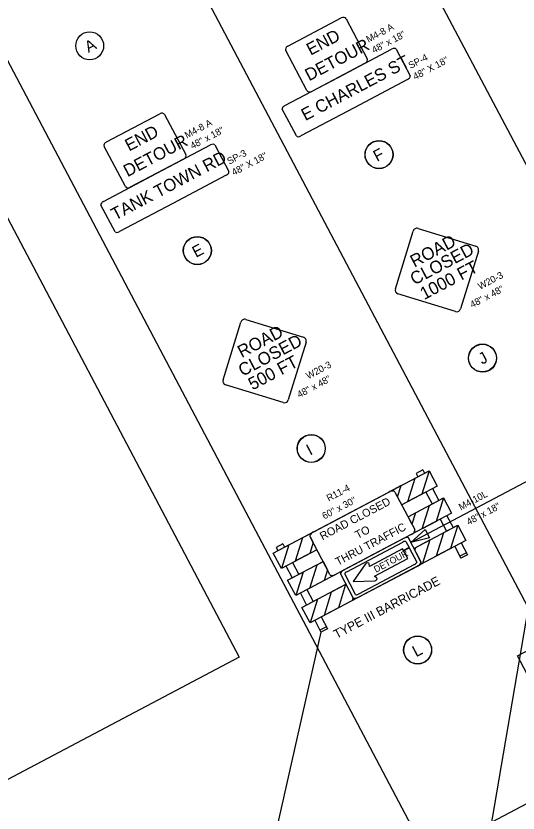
# Model space of a CAD drawing. Extents: x 1487176 to 2935813, y 497724 to 1002340.
# Drawn here: x 1488583 to 1489024, y 498480 to 499179 of the extents above; entities that cross this region are included whole.
import ezdxf

# ---------------------------------------------------------------- set-up
doc = ezdxf.new("R2010")
doc.units = 0
for name, color, linetype in [('DEV TYPE 3 BARRICADE WITH R11-4 M4-10L CELL', 7, 'Continuous'), ('Gray Area Fill Shapes', 7, 'Continuous'), ('GS M4-8 CELL', 7, 'Continuous'), ('Scratch_Level_0', 7, 'Continuous'), ('Scratch_Level_1', 7, 'Continuous'), ('Sheet Block Title CELL', 7, 'Continuous'), ('Sheet Breakdown Map CELL', 7, 'Continuous'), ('WZ OSDHWYEND CELL', 7, 'Continuous'), ('WZ OSDHWYR CELL', 7, 'Continuous'), ('WZ OSDHWYS CELL', 7, 'Continuous'), ('WZ OSDR CELL', 7, 'Continuous'), ('WZ RC1000 CELL', 7, 'Continuous'), ('WZ RC500 CELL', 7, 'Continuous')]:
    doc.layers.add(name, color=color, linetype=linetype)

msp = doc.modelspace()

# ---------------------------------------------------------------- linework, layer by layer
at = {"layer": 'DEV TYPE 3 BARRICADE WITH R11-4 M4-10L CELL'}
for p, q in [((1488809.03, 498707.77), (1488945.87, 498780.03)), ((1488933.56, 498773.53), (1488945.87, 498780.03)), ((1488940.27, 498780.78), (1488934.46, 498777.72)), ((1488934.46, 498777.72), (1488936, 498774.81)), ((1488945.87, 498780.03), (1488939.54, 498759.53)), ((1488940.27, 498780.78), (1488941.8, 498777.88)), ((1488945.87, 498780.03), (1488952.95, 498766.61)), ((1488921.24, 498767.02), (1488910.42, 498761.31)), ((1488918.17, 498757.08), (1488921.24, 498767.02)), ((1488927.22, 498753.02), (1488933.56, 498773.53)), ((1488929.73, 498717.15), (1489035.09, 498772.78)), ((1488915.89, 498761.41), (1488918.17, 498757.08)), ((1488915.89, 498761.41), (1488915.89, 498761.41)), ((1488952.95, 498766.61), (1488921.82, 498750.17)), ((1488943.08, 498761.4), (1488948.6, 498750.94)), ((1488948.89, 498764.46), (1488954.41, 498754.01)), ((1488939.54, 498759.53), (1488927.22, 498753.02)), ((1488927.34, 498739.72), (1488958.47, 498756.16)), ((1488946.16, 498749.65), (1488958.47, 498756.16)), ((1488958.47, 498756.16), (1488952.14, 498735.65)), ((1488958.47, 498756.16), (1488965.56, 498742.74)), ((1488939.83, 498729.15), (1488946.16, 498749.65)), ((1488965.56, 498742.74), (1488828.72, 498670.49)), ((1488927.34, 498739.72), (1488933.85, 498743.15)), ((1488930.78, 498733.21), (1488927.34, 498739.72)), ((1488933.85, 498743.15), (1488930.78, 498733.21)), ((1488961.49, 498740.59), (1488967.01, 498730.14)), ((1488932.49, 498711.91), (1488971.08, 498732.28)), ((1488952.14, 498735.65), (1488939.83, 498729.15)), ((1488955.69, 498737.53), (1488961.21, 498727.07)), ((1488958.77, 498725.78), (1488971.08, 498732.28)), ((1488971.08, 498732.28), (1488964.75, 498711.78)), ((1488971.08, 498732.28), (1488978.16, 498718.87)), ((1488834.99, 498721.48), (1488844.51, 498726.51)), ((1488952.43, 498705.28), (1488958.77, 498725.78)), ((1488828.66, 498700.98), (1488834.99, 498721.48)), ((1488841.31, 498722.04), (1488843.94, 498717.07)), ((1488978.16, 498718.87), (1488841.33, 498646.61)), ((1488934.14, 498712.78), (1488946.45, 498719.28)), ((1488946.45, 498719.28), (1488940.12, 498698.78)), ((1488809.03, 498707.77), (1488822.68, 498714.98)), ((1488817.37, 498715.89), (1488811.56, 498712.82)), ((1488811.56, 498712.82), (1488813.1, 498709.92)), ((1488822.68, 498714.98), (1488816.12, 498694.36)), ((1488817.37, 498715.89), (1488818.91, 498712.99)), ((1488843.94, 498717.07), (1488840.98, 498707.48)), ((1488873.57, 498691.42), (1488922.82, 498717.49)), ((1488922.6, 498711.42), (1488893.42, 498696.01)), ((1488923.35, 498709.99), (1488922.6, 498711.42)), ((1488928.3, 498712.61), (1488923.35, 498709.99)), ((1488923.43, 498709.84), (1488928.39, 498712.45)), ((1488925.51, 498717.9), (1488928.3, 498712.61)), ((1488928.39, 498712.45), (1488934.99, 498699.78)), ((1488933.36, 498710.26), (1488934.14, 498712.78)), ((1488964.75, 498711.78), (1488952.43, 498705.28)), ((1488968.29, 498713.65), (1488973.81, 498703.2)), ((1488974.1, 498716.72), (1488979.62, 498706.27)), ((1488816.12, 498694.36), (1488809.03, 498707.77)), ((1488816.12, 498694.36), (1488809.03, 498707.77)), ((1488847.25, 498710.79), (1488816.12, 498694.36)), ((1488840.98, 498707.48), (1488828.66, 498700.98)), ((1488927.09, 498702.91), (1488923.43, 498709.84)), ((1488938.43, 498700.67), (1488933.36, 498710.26)), ((1488978.7, 498708.01), (1488972.89, 498704.94)), ((1488979.62, 498706.27), (1488973.81, 498703.2)), ((1488821.64, 498683.9), (1488852.77, 498700.34)), ((1488825.99, 498699.57), (1488831.51, 498689.12)), ((1488841.27, 498677.11), (1488847.6, 498697.61)), ((1488847.6, 498697.61), (1488852.77, 498700.34)), ((1488890.13, 498698.42), (1488879.03, 498682.91)), ((1488933.12, 498697.83), (1488883.9, 498671.84)), ((1488893.42, 498696.01), (1488893.27, 498698.4)), ((1488897.92, 498687.51), (1488927.09, 498702.91)), ((1488940.12, 498698.78), (1488936.12, 498696.67)), ((1488820.18, 498696.5), (1488825.7, 498686.05)), ((1488821.64, 498683.9), (1488835.29, 498691.11)), ((1488835.29, 498691.11), (1488828.72, 498670.49)), ((1488883.39, 498668.83), (1488936.09, 498696.65)), ((1488828.72, 498670.49), (1488821.64, 498683.9)), ((1488828.72, 498670.49), (1488821.64, 498683.9)), ((1488853.58, 498683.61), (1488841.27, 498677.11)), ((1488881.29, 498671.43), (1488871.74, 498689.52)), ((1488879.03, 498682.91), (1488898.02, 498683.48)), ((1488899.77, 498686.08), (1488897.92, 498687.51)), ((1488834.24, 498660.03), (1488872.83, 498680.41)), ((1488860.2, 498673.74), (1488872.52, 498680.24)), ((1488872.52, 498680.24), (1488866.18, 498659.74)), ((1488832.79, 498672.63), (1488838.31, 498662.18)), ((1488838.6, 498675.7), (1488844.12, 498665.24)), ((1488853.87, 498653.24), (1488860.2, 498673.74)), ((1488834.24, 498660.03), (1488847.89, 498667.24)), ((1488847.89, 498667.24), (1488841.33, 498646.61)), ((1488883.39, 498668.83), (1488878.5, 498666.24)), ((1488878.5, 498666.24), (1488879.23, 498668.62)), ((1488841.33, 498646.61), (1488834.24, 498660.03)), ((1488841.33, 498646.61), (1488834.24, 498660.03)), ((1488866.18, 498659.74), (1488853.87, 498653.24)), ((1488845.39, 498648.76), (1488850.91, 498638.31)), ((1488851.2, 498651.83), (1488856.72, 498641.37)), ((1488855.8, 498643.12), (1488849.99, 498640.05)), ((1488856.72, 498641.37), (1488850.91, 498638.31))]:
    msp.add_line(p, q, dxfattribs=at)
for points in [[(1488844.51, 498726.51), (1488910.39, 498761.29)], [(1488915.89, 498761.41), (1488933.28, 498728.48)], [(1488858.7, 498689.1), (1488841.31, 498722.04)], [(1488930.08, 498724), (1488864.2, 498689.22)], [(1488923.49, 498720.52), (1488870.79, 498692.7)], [(1488938.89, 498699.8), (1488927.66, 498721.06)], [(1488852.77, 498700.34), (1488856.54, 498693.19), (1488853.58, 498683.61)], [(1488868, 498689.56), (1488879.23, 498668.3)]]:
    msp.add_lwpolyline(points, dxfattribs=at)
msp.add_lwpolyline([(1488946.16, 498721.18), (1488929.73, 498717.15), (1488942.33, 498728.44)], close=True, dxfattribs=at)
msp.add_lwpolyline([(1488946.16, 498721.18), (1488929.73, 498717.15), (1488942.33, 498728.44)], close=True, dxfattribs=at)
for centre, major_axis, ratio, start_param, end_param in [((1488911.54, 498759.12), (4.35, 2.3), 0.5, 0, 1.570796), ((1488911.54, 498759.12), (4.35, 2.3), 0.5, 0, 1.570881), ((1488845.66, 498724.33), (-4.35, -2.3), 0.5, 4.712162, 6.283185), ((1488845.66, 498724.33), (-4.35, -2.3), 0.5, 4.712162, 6.283185), ((1488928.93, 498726.18), (-4.35, -2.3), 0.5, 1.570796, 3.141593), ((1488923.21, 498716.69), (2.24, 1.18), 0.337508, 6.283183, 7.85379), ((1488924.18, 498719.22), (3.48, 1.84), 0.375009, 0, 1.571024), ((1488891.59, 498697.91), (-1.6, -0.84), 0.720018, 2.830616, 5.313575), ((1488932.72, 498698.59), (2.24, 1.18), 0.337508, 4.712575, 6.283183), ((1488934.95, 498698.83), (-3.48, -1.84), 0.625, 1.570796, 3.141593), ((1488935.4, 498697.96), (3.48, 1.84), 0.375009, 4.712389, 6.283185), ((1488871.48, 498691.39), (-3.48, -1.84), 0.375009, 4.712389, 6.283185), ((1488873.98, 498690.7), (-2.24, -1.18), 0.337508, 4.712198, 6.283193), ((1488863.05, 498691.4), (-4.35, -2.3), 0.5, 0, 1.570796), ((1488898.45, 498684.92), (-1.6, -0.84), 0.720018, 0.969609, 3.452568), ((1488883.5, 498672.6), (-2.24, -1.18), 0.337508, 0.000008, 1.570982), ((1488882.71, 498670.13), (3.48, 1.84), 0.375009, 3.141593, 4.712389), ((1488882.25, 498671), (-3.48, -1.84), 0.625, 0.287132, 1.570688)]:
    msp.add_ellipse(centre, major_axis=major_axis, ratio=ratio, start_param=start_param, end_param=end_param, dxfattribs=at)
at = {"layer": 'Gray Area Fill Shapes'}
for centre in [(1488647.85, 499153.04), (1488901.93, 499057.44), (1488742.4, 498973.2), (1488992.75, 498878.86), (1488842.42, 498799.48), (1488935.81, 498622.62)]:
    msp.add_circle(centre, 12.25, dxfattribs=at)
at = {"layer": 'GS M4-8 CELL'}
for p, q in [((1488866.09, 499125.3), (1488912.96, 499150.05)), ((1488926.97, 499123.52), (1488880.1, 499098.77)), ((1488880.1, 499098.77), (1488833.23, 499074.03)), ((1488706.92, 499041.26), (1488753.79, 499066.01)), ((1488767.8, 499039.48), (1488720.93, 499014.73)), ((1488720.93, 499014.73), (1488674.06, 498989.98))]:
    msp.add_line(p, q, dxfattribs=at)
for points in [[(1488916.87, 499150.14), (1488929.25, 499126.71)], [(1488819.22, 499100.55), (1488866.09, 499125.3)], [(1488829.32, 499073.94), (1488816.94, 499097.37)], [(1488757.7, 499066.09), (1488770.07, 499042.66)], [(1488660.05, 499016.51), (1488706.92, 499041.26)], [(1488670.15, 498989.89), (1488657.77, 499013.33)]]:
    msp.add_lwpolyline(points, dxfattribs=at)
for centre, major_axis, start_param, end_param in [((1488913.78, 499148.51), (3.1, 1.63), 0, 1.570796), ((1488926.15, 499125.07), (-3.1, -1.63), 1.570796, 3.141593), ((1488820.04, 499099.01), (-3.1, -1.63), 4.712162, 6.283185), ((1488832.41, 499075.57), (-3.1, -1.63), 0, 1.570796), ((1488754.61, 499064.46), (3.1, 1.63), 0, 1.570796), ((1488766.98, 499041.03), (-3.1, -1.63), 1.570796, 3.141593), ((1488660.87, 499014.96), (-3.1, -1.63), 4.712162, 6.283185), ((1488673.24, 498991.53), (-3.1, -1.63), 0, 1.570796)]:
    msp.add_ellipse(centre, major_axis=major_axis, ratio=0.5, start_param=start_param, end_param=end_param, dxfattribs=at)
at = {"layer": 'Scratch_Level_0'}
msp.add_lwpolyline([(1489096.07, 499596.4), (1487858.05, 498942.7), (1488301.64, 498102.61), (1489078.8, 498512.98), (1489023.58, 498617.56), (1489484.43, 498860.9)], close=True, dxfattribs=at)
at = {"layer": 'Scratch_Level_1'}
for p, q in [((1488746.22, 499587.89), (1489286.34, 498565)), ((1488587.05, 499503.85), (1489127.16, 498480.95)), ((1488427.88, 499419.8), (1488967.99, 498396.91)), ((1489085.53, 498970.89), (1488904.96, 497908.56)), ((1488850.91, 498638.31), (1488644.26, 497723.78))]:
    msp.add_line(p, q, dxfattribs=at)
at = {"layer": 'Sheet Breakdown Map CELL'}
msp.add_lwpolyline([(1487877.32, 498940.19), (1488411.84, 499222.43), (1488476.37, 499100.21), (1488513.39, 499119.76), (1488779.21, 498616.34), (1488207.67, 498314.56)], close=True, dxfattribs=at)
msp.add_lwpolyline([(1487877.32, 498940.19), (1488411.84, 499222.43), (1488476.37, 499100.21), (1488513.39, 499119.76), (1488779.21, 498616.34), (1488207.67, 498314.56)], close=True, dxfattribs=at)
at = {"layer": 'WZ OSDHWYEND CELL'}
for points in [[(1488821.85, 499152.83), (1488868.72, 499177.58)], [(1488873.04, 499176.89), (1488891.6, 499141.74)], [(1488838.54, 499113.72), (1488819.98, 499148.88)], [(1488889.73, 499137.78), (1488842.86, 499113.04)], [(1488662.47, 499068.68), (1488709.34, 499093.42)], [(1488713.66, 499092.73), (1488732.22, 499057.59)], [(1488679.17, 499029.57), (1488660.6, 499064.72)], [(1488730.35, 499053.63), (1488683.49, 499028.88)]]:
    msp.add_lwpolyline(points, dxfattribs=at)
for centre, major_axis, start_param, end_param in [((1488869.94, 499175.26), (3.1, 1.63), 0, 1.570796), ((1488823.08, 499150.51), (-3.1, -1.63), 4.712162, 6.283185), ((1488888.5, 499140.11), (-3.1, -1.63), 1.570796, 3.141593), ((1488841.64, 499115.36), (-3.1, -1.63), 0, 1.570796), ((1488710.57, 499091.1), (3.1, 1.63), 0, 1.570796), ((1488663.7, 499066.35), (-3.1, -1.63), 4.712162, 6.283185), ((1488729.13, 499055.95), (-3.1, -1.63), 1.570796, 3.141593), ((1488682.26, 499031.2), (-3.1, -1.63), 0, 1.570796)]:
    msp.add_ellipse(centre, major_axis=major_axis, ratio=0.75, start_param=start_param, end_param=end_param, dxfattribs=at)
at = {"layer": 'WZ OSDHWYR CELL'}
msp.add_circle((1488647.85, 499153.04), 12.25, dxfattribs=at)
at = {"layer": 'WZ OSDHWYS CELL'}
for centre in [(1488901.81, 499057.65), (1488742.28, 498973.42), (1488992.64, 498879.07), (1488842.31, 498799.69), (1488935.69, 498622.84)]:
    msp.add_circle(centre, 12.25, dxfattribs=at)
at = {"layer": 'WZ RC1000 CELL'}
for points in [[(1488936.22, 498992.8), (1488986.86, 498977.16)], [(1488916.2, 498939.85), (1488931.85, 498990.49)], [(1488989.17, 498972.78), (1488973.53, 498922.14)], [(1488969.15, 498919.83), (1488918.51, 498935.47)]]:
    msp.add_lwpolyline(points, dxfattribs=at)
for centre, start, end in [((1488935.19, 498989.46), 72.82206, 162.83509), ((1488985.83, 498973.82), 342.83509, 72.83509), ((1488919.55, 498938.82), 162.83509, 252.83509), ((1488970.19, 498923.18), 252.83509, 342.83509)]:
    msp.add_arc(centre, 3.5, start, end, dxfattribs=at)
at = {"layer": 'WZ RC500 CELL'}
for points in [[(1488764.9, 498859.91), (1488780.54, 498910.55)], [(1488784.91, 498912.86), (1488835.55, 498897.22)], [(1488837.86, 498892.84), (1488822.22, 498842.21)], [(1488817.85, 498839.89), (1488767.21, 498855.53)]]:
    msp.add_lwpolyline(points, dxfattribs=at)
for centre, start, end in [((1488783.88, 498909.52), 72.82206, 162.83509), ((1488834.52, 498893.88), 342.83509, 72.83509), ((1488768.24, 498858.88), 162.83509, 252.83509), ((1488818.88, 498843.24), 252.83509, 342.83509)]:
    msp.add_arc(centre, 3.5, start, end, dxfattribs=at)

# ---------------------------------------------------------------- texts
at = {"layer": 'DEV TYPE 3 BARRICADE WITH R11-4 M4-10L CELL'}
for s, height, p in [('R11-4', 6, (1488857.73, 498752.88)), ('M4-10L', 6, (1488973.72, 498745.09)), ('ROAD CLOSED', 7.0305, (1488852.18, 498718.92)), ("60'' x 30''", 6, (1488853.86, 498737.22)), ('48" x 18"', 6, (1488980.58, 498732.1)), ('THRU TRAFFIC', 7.0305, (1488865.83, 498696.58)), ('TO', 7.031, (1488883.16, 498720.05)), ('DETOUR', 5.799, (1488899.15, 498690.42)), ('TYPE III BARRICADE', 7.8816, (1488864.61, 498632.38))]:
    msp.add_text(s, height=height, rotation=27.83509, dxfattribs=at).set_placement(p)
at = {"layer": 'GS M4-8 CELL'}
for s, height, p in [('E CHARLES ST', 10.8304, (1488837.16, 499086.94)), ('SP-4', 6, (1488929.63, 499132.72)), ("48'' X 18''", 6.0002, (1488933.66, 499122.98)), ('SP-3', 6, (1488770.46, 499048.67)), ('TANK TOWN RD', 10.8304, (1488670.21, 498999.55)), ("48'' X 18''", 6.0002, (1488774.48, 499038.93))]:
    msp.add_text(s, height=height, rotation=27.83543, dxfattribs=at).set_placement(p)
at = {"layer": 'Sheet Block Title CELL'}
for s, height, p in [('10735 DAVID TAYLOR DRIVE, SUITE 310   CHARLOTTE, NC 28262', 2.9167, (1489000.03, 498435.55)), ('A. MORTON THOMAS AND ASSOCIATES, INC.', 3.75, (1489003.02, 498442.55))]:
    msp.add_text(s, height=height, rotation=27.83461, dxfattribs=at).set_placement(p)
at = {"layer": 'WZ OSDHWYEND CELL'}
for s, height, p in [('END', 10.83, (1488841.77, 499144.34)), ('M4-8 A', 6, (1488892.53, 499155.72)), ('48" x 18"', 6, (1488897.49, 499146.32)), ('DETOUR', 10.83, (1488840.45, 499121.86)), ('END', 10.83, (1488682.39, 499060.19)), ('M4-8 A', 6, (1488733.16, 499071.56)), ('48" x 18"', 6, (1488738.12, 499062.17)), ('DETOUR', 10.83, (1488681.07, 499037.71))]:
    msp.add_text(s, height=height, rotation=27.83509, dxfattribs=at).set_placement(p)
at = {"layer": 'WZ OSDHWYS CELL'}
msp.add_text('F', height=10, rotation=27.83509, dxfattribs=at).set_placement((1488900.13, 499051.11))
at = {"layer": 'WZ OSDR CELL'}
for s, p in [('A', (1488646.75, 499146.8)), ('E', (1488741.13, 498966.88)), ('J', (1488992.38, 498873.01)), ('I', (1488841.29, 498793.23)), ('L', (1488934.42, 498616.23))]:
    msp.add_text(s, height=10, rotation=27.83509, dxfattribs=at).set_placement(p)
at = {"layer": 'WZ RC1000 CELL'}
for s, height, p in [('ROAD', 11, (1488932.9, 498958.28)), ('CLOSED', 11, (1488932.88, 498942.7)), ('1000 FT', 11, (1488941.53, 498929.83)), ('W20-3', 6, (1488990.66, 498938.85)), ('48" x 48"', 6, (1488983.74, 498922.77))]:
    msp.add_text(s, height=height, rotation=27.83509, dxfattribs=at).set_placement(p)
at = {"layer": 'WZ RC500 CELL'}
for s, height, p in [('ROAD', 11, (1488781.33, 498878.84)), ('CLOSED', 11, (1488782.02, 498862.55)), ('500 FT', 11, (1488790.78, 498850.45)), ('W20-3', 6, (1488839.77, 498860.27)), ('48" x 48"', 6, (1488831.89, 498843.86))]:
    msp.add_text(s, height=height, rotation=27.83509, dxfattribs=at).set_placement(p)

doc.saveas('drawing.dxf')
